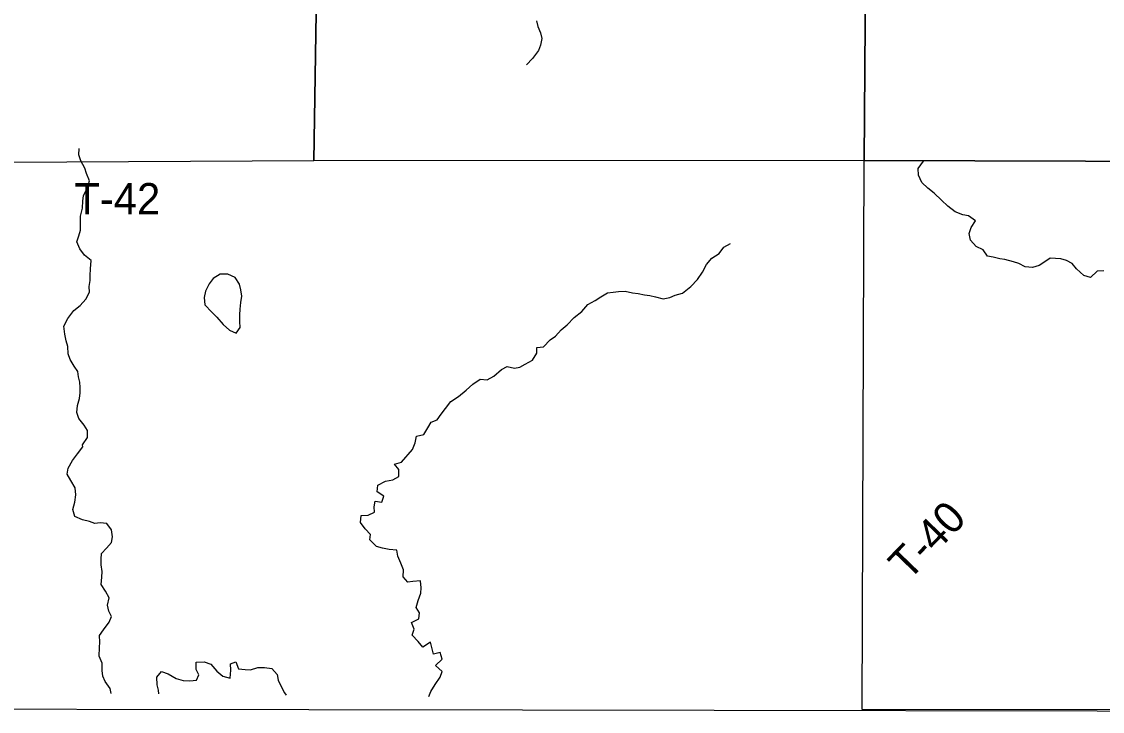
# Model space of a CAD drawing. Extents: x 1772825 to 1773716, y 1138558 to 1139032.
# Drawn here: x 1772828.204 to 1772829.187, y 1138558.123 to 1138558.75 of the extents above; entities that cross this region are included whole.
import ezdxf

# ---------------------------------------------------------------- set-up
doc = ezdxf.new("R2010")
doc.units = 0
for name, color, linetype in [('GM_X_Minor_Lake', 7, 'Continuous'), ('GM_X_Minor_River', 7, 'Continuous'), ('GM_X_Section', 7, 'Continuous'), ('GM_X_Township', 7, 'Continuous'), ('GM_X_Township_Road_Text', 7, 'Continuous')]:
    doc.layers.add(name, color=color, linetype=linetype)

msp = doc.modelspace()

# ---------------------------------------------------------------- linework, layer by layer
at = {"layer": 'GM_X_Minor_Lake'}
for points in [[(1772828.38938, 1138558.52036), (1772828.38475, 1138558.5204), (1772828.37828, 1138558.51646), (1772828.37482, 1138558.51155), (1772828.37136, 1138558.50494), (1772828.37018, 1138558.49906), (1772828.37089, 1138558.49242), (1772828.37711, 1138558.48592), (1772828.38162, 1138558.48114), (1772828.38746, 1138558.47465), (1772828.39311, 1138558.46929), (1772828.39916, 1138558.46659)], [(1772828.39916, 1138558.46659), (1772828.40281, 1138558.47188), (1772828.40266, 1138558.47738), (1772828.40251, 1138558.48345), (1772828.40293, 1138558.48857), (1772828.40354, 1138558.49464), (1772828.40434, 1138558.50033), (1772828.40343, 1138558.50621), (1772828.40233, 1138558.51116), (1772828.3982, 1138558.51745), (1772828.39158, 1138558.52034), (1772828.38938, 1138558.52036)]]:
    msp.add_lwpolyline(points, dxfattribs=at)
at = {"layer": 'GM_X_Minor_River'}
for points in [[(1772828.67253, 1138558.75084), (1772828.67363, 1138558.74571), (1772828.67606, 1138558.74), (1772828.67735, 1138558.73468), (1772828.67617, 1138558.72881), (1772828.67423, 1138558.72389), (1772828.66868, 1138558.71672), (1772828.66333, 1138558.71088)], [(1772828.25972, 1138558.36313), (1772828.25955, 1138558.36519), (1772828.26396, 1138558.3718), (1772828.264, 1138558.37806), (1772828.261, 1138558.38282), (1772828.25611, 1138558.38893), (1772828.25445, 1138558.39445), (1772828.25506, 1138558.40089), (1772828.25663, 1138558.40733), (1772828.25742, 1138558.41245), (1772828.25746, 1138558.41719), (1772828.25692, 1138558.42213), (1772828.25582, 1138558.42707), (1772828.25529, 1138558.43182), (1772828.25191, 1138558.43678), (1772828.24816, 1138558.44269), (1772828.2463, 1138558.44801), (1772828.24597, 1138558.45466), (1772828.24467, 1138558.4596), (1772828.24339, 1138558.46568), (1772828.2425, 1138558.47309), (1772828.24615, 1138558.48008), (1772828.25152, 1138558.48725), (1772828.25724, 1138558.49176), (1772828.26259, 1138558.4976), (1772828.26587, 1138558.50403), (1772828.26552, 1138558.50915), (1772828.26651, 1138558.51446), (1772828.26655, 1138558.5192), (1772828.26678, 1138558.52527), (1772828.2674, 1138558.53285), (1772828.26137, 1138558.53764), (1772828.25704, 1138558.54337), (1772828.25444, 1138558.54984), (1772828.25599, 1138558.55533), (1772828.25755, 1138558.56044), (1772828.25764, 1138558.57315), (1772828.2594, 1138558.58035), (1772828.25983, 1138558.58698), (1772828.26024, 1138558.59172), (1772828.2639, 1138558.59929), (1772828.26584, 1138558.60534), (1772828.26323, 1138558.612), (1772828.26156, 1138558.61676), (1772828.25782, 1138558.62343), (1772828.25615, 1138558.62894), (1772828.25657, 1138558.63482)], [(1772829.18864, 1138558.52346), (1772829.18237, 1138558.52294), (1772829.17645, 1138558.51729), (1772829.17039, 1138558.51923), (1772829.1638, 1138558.52535), (1772829.15966, 1138558.53013), (1772829.15474, 1138558.53282), (1772829.14944, 1138558.53438), (1772829.14451, 1138558.5346), (1772829.13977, 1138558.53502), (1772829.13481, 1138558.53145), (1772829.12967, 1138558.52826), (1772829.12358, 1138558.52641), (1772829.11714, 1138558.52703), (1772829.11128, 1138558.53011), (1772829.10636, 1138558.53167), (1772829.09859, 1138558.53362), (1772829.09386, 1138558.53442), (1772829.08779, 1138558.53579), (1772829.08268, 1138558.53659), (1772829.07874, 1138558.5425), (1772829.0725, 1138558.54558), (1772829.06742, 1138558.55131), (1772829.06613, 1138558.55739), (1772829.06788, 1138558.56269), (1772829.07172, 1138558.56892), (1772829.0653, 1138558.57353), (1772829.06018, 1138558.57432), (1772829.05337, 1138558.57703), (1772829.04658, 1138558.5822), (1772829.04074, 1138558.58775), (1772829.03415, 1138558.59406), (1772829.02849, 1138558.59866), (1772829.02302, 1138558.60382), (1772829.02004, 1138558.61029), (1772829.0197, 1138558.61656), (1772829.02449, 1138558.62316)], [(1772828.55966, 1138558.36084), (1772828.56217, 1138558.36689), (1772828.56316, 1138558.37296), (1772828.57, 1138558.37442), (1772828.57346, 1138558.38047), (1772828.57673, 1138558.38576), (1772828.58205, 1138558.38781), (1772828.5857, 1138558.39309), (1772828.58972, 1138558.39799), (1772828.59451, 1138558.4046), (1772828.60137, 1138558.4091), (1772828.60862, 1138558.41493), (1772828.61454, 1138558.42019), (1772828.62122, 1138558.4247), (1772828.62747, 1138558.42408), (1772828.63376, 1138558.42764), (1772828.64063, 1138558.43347), (1772828.64578, 1138558.43647), (1772828.65259, 1138558.4349), (1772828.65734, 1138558.43581), (1772828.6623, 1138558.43843), (1772828.66877, 1138558.44218), (1772828.6728, 1138558.44841), (1772828.67284, 1138558.45353), (1772828.67892, 1138558.45424), (1772828.68484, 1138558.46065), (1772828.6898, 1138558.46403), (1772828.69478, 1138558.46968), (1772828.7005, 1138558.47419), (1772828.70681, 1138558.48078), (1772828.71368, 1138558.48624), (1772828.71904, 1138558.49265), (1772828.7257, 1138558.49639), (1772828.73085, 1138558.49958), (1772828.73714, 1138558.50332), (1772828.74227, 1138558.50404), (1772828.7472, 1138558.50458), (1772828.75309, 1138558.50491), (1772828.75991, 1138558.50334), (1772828.76483, 1138558.50274), (1772828.77071, 1138558.50155), (1772828.77564, 1138558.50095), (1772828.78075, 1138558.49958), (1772828.78757, 1138558.49801), (1772828.79364, 1138558.49911), (1772828.7986, 1138558.50134), (1772828.80525, 1138558.50319), (1772828.81288, 1138558.50921), (1772828.81881, 1138558.51542), (1772828.8236, 1138558.52203), (1772828.82725, 1138558.52902), (1772828.83204, 1138558.53487), (1772828.83852, 1138558.53918), (1772828.84274, 1138558.54503), (1772828.84883, 1138558.5484)], [(1772828.28567, 1138558.13897), (1772828.28464, 1138558.14338), (1772828.27995, 1138558.14968), (1772828.2781, 1138558.15463), (1772828.27738, 1138558.15976), (1772828.27725, 1138558.16641), (1772828.27465, 1138558.17289), (1772828.2749, 1138558.18067), (1772828.27533, 1138558.1856), (1772828.27481, 1138558.19168), (1772828.27846, 1138558.19677), (1772828.28383, 1138558.20375), (1772828.28577, 1138558.20886), (1772828.28334, 1138558.21363), (1772828.28206, 1138558.21914), (1772828.28383, 1138558.22596), (1772828.28028, 1138558.23207), (1772828.27634, 1138558.23798), (1772828.27716, 1138558.24462), (1772828.27739, 1138558.24974), (1772828.2765, 1138558.25601), (1772828.27654, 1138558.26114), (1772828.27678, 1138558.26607), (1772828.28118, 1138558.27097), (1772828.28597, 1138558.27625), (1772828.28677, 1138558.28137), (1772828.28587, 1138558.28764), (1772828.28156, 1138558.29337), (1772828.2755, 1138558.29399), (1772828.27075, 1138558.29365), (1772828.26584, 1138558.2954), (1772828.25959, 1138558.29697), (1772828.2526, 1138558.29987), (1772828.25057, 1138558.30615), (1772828.25252, 1138558.31297), (1772828.25353, 1138558.31961), (1772828.25282, 1138558.32607), (1772828.24871, 1138558.33256), (1772828.24553, 1138558.33828), (1772828.24653, 1138558.34396), (1772828.25038, 1138558.35077), (1772828.25498, 1138558.3568), (1772828.25972, 1138558.36313)], [(1772828.52742, 1138558.32228), (1772828.52823, 1138558.32835), (1772828.53509, 1138558.3319), (1772828.54174, 1138558.33318), (1772828.54708, 1138558.33636), (1772828.54732, 1138558.34262), (1772828.54338, 1138558.3474), (1772828.54965, 1138558.34944), (1772828.55966, 1138558.36084)], [(1772828.57457, 1138558.13619), (1772828.57631, 1138558.1406), (1772828.58035, 1138558.14702), (1772828.58496, 1138558.15362), (1772828.58671, 1138558.15873), (1772828.5805, 1138558.16429), (1772828.58662, 1138558.17012), (1772828.58477, 1138558.17602), (1772828.57888, 1138558.17474), (1772828.5774, 1138558.1795), (1772828.57594, 1138558.18559), (1772828.56907, 1138558.1809), (1772828.56494, 1138558.18625), (1772828.55949, 1138558.1918), (1772828.56106, 1138558.19748), (1772828.55883, 1138558.20357), (1772828.56531, 1138558.20675), (1772828.56612, 1138558.21224), (1772828.56293, 1138558.21702), (1772828.56488, 1138558.22345), (1772828.56722, 1138558.23008), (1772828.56764, 1138558.23482), (1772828.56693, 1138558.24128), (1772828.5601, 1138558.24077), (1772828.55536, 1138558.24024), (1772828.55104, 1138558.24502), (1772828.55147, 1138558.25128), (1772828.54905, 1138558.25737), (1772828.54645, 1138558.26385), (1772828.54536, 1138558.26917), (1772828.53854, 1138558.2698), (1772828.53229, 1138558.27099), (1772828.52681, 1138558.27255), (1772828.52098, 1138558.27868), (1772828.5214, 1138558.28361), (1772828.51651, 1138558.28858), (1772828.51239, 1138558.29431), (1772828.51301, 1138558.30076), (1772828.51946, 1138558.30109), (1772828.52518, 1138558.3037), (1772828.52484, 1138558.30864), (1772828.52564, 1138558.31395), (1772828.5317, 1138558.31276), (1772828.53346, 1138558.31844), (1772828.52742, 1138558.32228)], [(1772828.3288, 1138558.13855), (1772828.32863, 1138558.14188), (1772828.32753, 1138558.14682), (1772828.32702, 1138558.15366), (1772828.33124, 1138558.15894), (1772828.33748, 1138558.15661), (1772828.34465, 1138558.15238), (1772828.35108, 1138558.1508), (1772828.35715, 1138558.15037), (1772828.36322, 1138558.15089), (1772828.36516, 1138558.15581), (1772828.36274, 1138558.16058), (1772828.36298, 1138558.16722), (1772828.37, 1138558.16773), (1772828.37624, 1138558.1654), (1772828.38169, 1138558.15928), (1772828.38715, 1138558.15449), (1772828.39377, 1138558.15273), (1772828.3944, 1138558.15994), (1772828.39407, 1138558.16583), (1772828.39902, 1138558.16749), (1772828.40124, 1138558.16121), (1772828.4075, 1138558.16078), (1772828.41224, 1138558.16036), (1772828.41889, 1138558.16258), (1772828.42496, 1138558.16253), (1772828.43159, 1138558.16172), (1772828.43648, 1138558.15617), (1772828.43738, 1138558.15085), (1772828.43999, 1138558.14589), (1772828.44316, 1138558.13942), (1772828.4446, 1138558.13744)]]:
    msp.add_lwpolyline(points, dxfattribs=at)
at = {"layer": 'GM_X_Section'}
for points in [[(1772827.96782, 1138559.12738), (1772827.96764, 1138559.12908), (1772828.47764, 1138559.12426), (1772828.47004, 1138558.62357), (1772827.96416, 1138558.62078)], [(1772828.97422, 1138559.1237), (1772828.97061, 1138558.62373), (1772828.47004, 1138558.62357), (1772828.47764, 1138559.12426)], [(1772829.48049, 1138559.12534), (1772829.47419, 1138558.62217), (1772828.97061, 1138558.62373), (1772828.97422, 1138559.1237)], [(1772829.47419, 1138558.62217), (1772829.47084, 1138558.12362), (1772828.96875, 1138558.12423), (1772828.97061, 1138558.62373)]]:
    msp.add_lwpolyline(points, close=True, dxfattribs=at)
at = {"layer": 'GM_X_Township'}
msp.add_lwpolyline([(1772829.35677, 1138558.12255), (1772828.65972, 1138558.1236), (1772828.46538, 1138558.12388), (1772828.04276, 1138558.12453), (1772827.9602, 1138558.12465), (1772827.96578, 1138558.87412), (1772827.96954, 1138559.37836), (1772827.97328, 1138559.62742), (1772827.97337, 1138559.80486), (1772827.97201, 1138559.91528), (1772827.97425, 1138560.12644), (1772827.9761, 1138560.40209), (1772827.97721, 1138560.57985), (1772827.98261, 1138561.13548), (1772828.37391, 1138561.13581), (1772828.73894, 1138561.13584), (1772828.93513, 1138561.13617), (1772829.26496, 1138561.13428)], dxfattribs=at)

# ---------------------------------------------------------------- texts
at = {"layer": 'GM_X_Township_Road_Text'}
for s, rotation, p in [('T-42', 0.00001, (1772828.25208, 1138558.57482)), ('T-40', 45.99699, (1772829.01075, 1138558.24057))]:
    msp.add_text(s, height=0.028409, rotation=rotation, dxfattribs=at).set_placement(p)

doc.saveas('drawing.dxf')
